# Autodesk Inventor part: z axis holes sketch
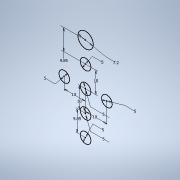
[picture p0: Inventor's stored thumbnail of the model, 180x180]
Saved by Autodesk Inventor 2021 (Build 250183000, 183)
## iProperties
Created: 2026-11
Part Number: z axis holes sketch
Material: Generic
Document SubType Name: Modeling
Designer: hp
Density: 1 g/cm^3
Appearance: Default
Author: hp
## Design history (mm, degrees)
sketch "Sketch1"
  geometry: C1 r 3.6 at (0, 19.85); C2 r 2.5 at (0, -10); C3 r 2.5 at (10, 0); C4 r 2.5 at (0, -19.85); C5 r 2.5 at (0, 10); C6 r 2.5 at (-10, 0); C7 r 2.5 at (0, 0); 2 further points
  constraints: 7 centre point, 4 vertical alignment, 2 coincident, 2 horizontal alignment
  dimensions: "d0" = 5 diameter of C2; "d1" = 5 diameter of C7; "d3" = 10 distance of point (0, 0) C3.centre; "d4" = 10 distance of point (0, 0) C6.centre; "d5" = 5 diameter of C6; "d6" = 5 diameter of C3; "d7" = 10 distance of point (0, 0) C5.centre; "d8" = 5 diameter of C5; "d9" = 5 diameter of C4; "d10" = 7.2 diameter of C1; "d12" = 10 distance of point (0, 0) C2.centre; "d13" = 9.85 distance of C5.centre C1.centre; "d14" = 9.85 distance of C2.centre C4.centre
